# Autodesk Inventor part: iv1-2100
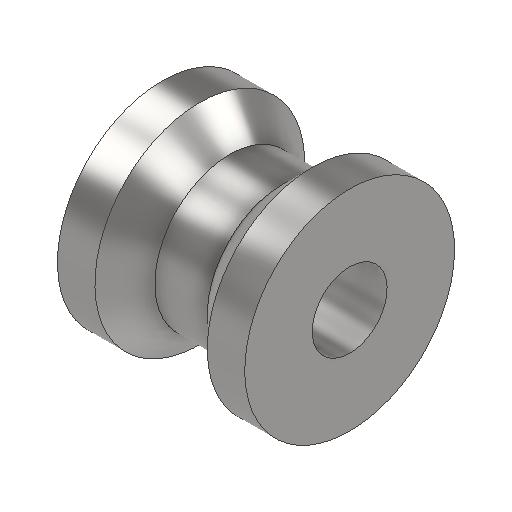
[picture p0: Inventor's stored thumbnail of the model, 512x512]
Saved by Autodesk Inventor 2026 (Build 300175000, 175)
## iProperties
Created: 2022-01
Part Number: iv1-2100
Material: Steel, Mild
Document SubType Name: Modeling
Designer: Lars Bertram Pedersen
Density: 7.85 g/cm^3
Appearance: Semi-Polished
Mass: 9857.41 g
Surface Area: 1008.08 cm^2
Volume: 1255.72 cm^3
Author: Lars Bertram Pedersen
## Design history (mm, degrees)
revolve "Revolution1" stored, may be unused: angle "d5" = 90 deg
fillet "Fillet1" dims "d14" = 2, "d15" = 2
body "Solid1"
sketch "Sketch1"
  geometry: L1 (0, 0)-(125, 0); L2 (0, 25)-(0, 70); L3 (0, 70)-(25, 70); L4 (25, 70)-(45, 50); L5 (45, 50)-(80, 50); L6 (80, 50)-(100, 70); L7 (100, 70)-(125, 70); L8 (125, 70)-(125, 25); L9 (125, 25)-(0, 25)
  constraints: 18 end point, 3 perpendicular, 2 equal length, 2 point on line, 2 vertical alignment, 1 horizontal, 1 parallel, 1 vertical
  dimensions: "d0" = 125 distance of L1.start L1.end; "d1" = 140 diameter of L3 L1; "d2" = 50 diameter of L9 L1; "d4" = 25 distance of L2.end L3.end; "d11" = 100 diameter of L5 L1; "d13" = 45 deg angle of L8 L6
